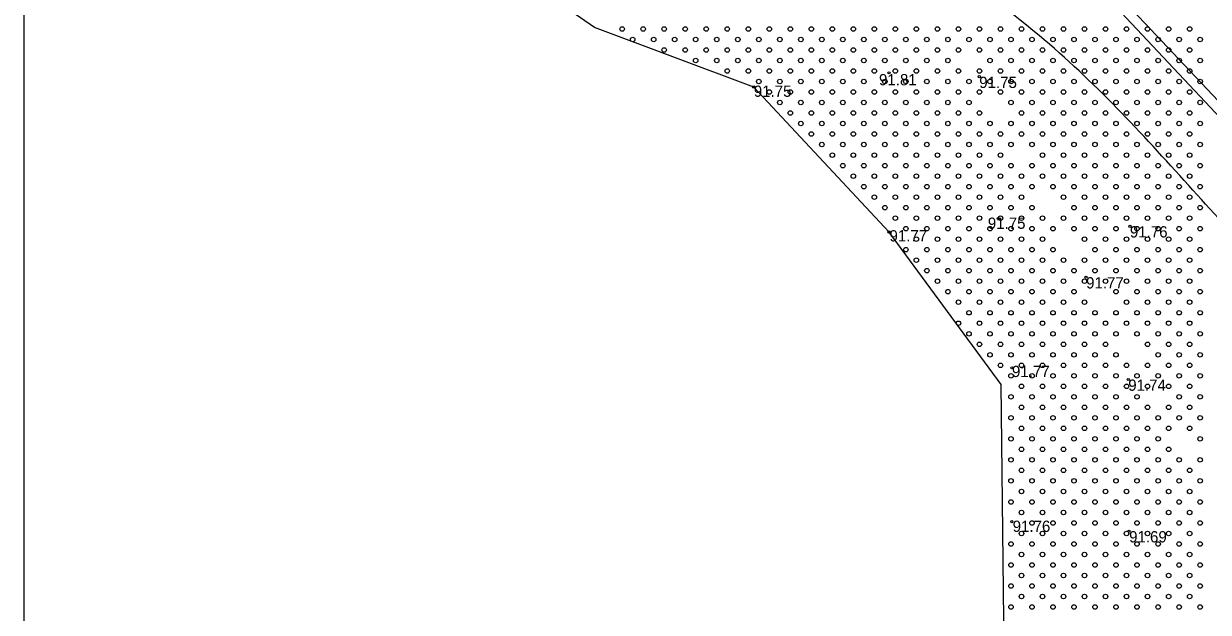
# Model space of a CAD drawing. Extents: x 316000 to 728450, y 314368 to 726000.
# Drawn here: x 725371.7 to 725766.2, y 315036.8 to 315232.8 of the extents above; entities that cross this region are included whole.
import ezdxf

# ---------------------------------------------------------------- set-up
doc = ezdxf.new("R2010")
doc.units = 0
for name, color, linetype in [('HIDG_GRAV_####_####_#', 7, 'Continuous'), ('RAMI_PLAN_####_TKST_#', 7, 'Continuous'), ('RAMI_UZMR_####_####_#', 7, 'Continuous'), ('RELJ_AATZ_####_TKST_#', 7, 'Continuous'), ('RELJ_ELEM_####_####_#', 7, 'Continuous'), ('RELJ_HORZ_PAMT_####_#', 7, 'Continuous'), ('RELJ_NOGA_####_####_#', 7, 'Continuous'), ('TERT_ELEM_####_####_#', 7, 'Continuous'), ('TERT_KONT_####_####_#', 7, 'Continuous')]:
    doc.layers.add(name, color=color, linetype=linetype)

msp = doc.modelspace()

# ---------------------------------------------------------------- linework, layer by layer
at = {"layer": 'HIDG_GRAV_####_####_#'}
for points in [[(725550.64, 315437.37), (725654.91, 315324.09), (725793.17, 315176.93), (726030.02, 314925.45), (726035.1, 314929.94), (725796.17, 315178.83)], [(725655.9, 315327.28), (725718.48, 315261.22), (725796.17, 315178.83)]]:
    msp.add_lwpolyline(points, dxfattribs=at)
at = {"layer": 'RAMI_PLAN_####_TKST_#'}
msp.add_lwpolyline([(725371.66, 314368.28), (727955.92, 314368.28), (727955.92, 316766.42), (725371.66, 316766.42)], close=True, dxfattribs=at)
at = {"layer": 'RAMI_UZMR_####_####_#'}
msp.add_lwpolyline([(727254.69, 315085.95), (727002.7, 315002.84), (726508.21, 314868.03), (726416.7, 314837.05), (725982.38, 314530.96), (725916.44, 314513.26), (725799.16, 314549.2), (725735.9, 314623.63), (725701.82, 314711.1), (725697.25, 315112.64), (725659.91, 315163.35), (725614.81, 315211.65), (725561.8, 315231.45), (725500.09, 315274.21), (725474.77, 315308.26), (725484.26, 315374.77), (725505.03, 315405.04), (725554.87, 315404.25), (725559.14, 315567.14), (725558.67, 315591.68), (725662, 315676.73), (726089.69, 315915.19)], dxfattribs=at)
at = {"layer": 'RELJ_ELEM_####_####_#'}
for centre in [(725659.91, 315216.38), (725689.93, 315215.09), (725614.81, 315211.65), (725696.3, 315167.87), (725659.91, 315163.35), (725740.11, 315165.31), (725725.51, 315148.34), (725700.78, 315118.15), (725739.55, 315114.26), (725700.78, 315066.95), (725739.84, 315063.77)]:
    msp.add_circle(centre, 0.375, dxfattribs=at)
at = {"layer": 'RELJ_HORZ_PAMT_####_#'}
msp.add_spline([(726081.57, 315247.05), (726057.5, 315241.5), (726036.5, 315213.5), (725977, 315161), (725966.5, 315108.5), (725903.5, 315045.5), (725862.12, 315076.6), (725805.5, 315130), (725759.7, 315178.88), (725709.89, 315228.8), (725646.99, 315287.19), (725634.68, 315314.96), (725629.04, 315327.48), (725557.35, 315340.26), (725478.3, 315344.16)], degree=3, dxfattribs=at)
at = {"layer": 'RELJ_NOGA_####_####_#'}
for points in [[(726259.12, 315084.51), (726262.72, 315089.26), (726261.56, 315090.84), (726260.2, 315092.42), (726257.29, 315095.53), (726218.91, 315136.38), (726180.31, 315176.84), (726128.67, 315229.97), (726063.7, 315298.11), (725999.9, 315366.09), (725937.21, 315432.09), (725876.35, 315495.23), (725810.58, 315563.08), (725744.7, 315632.91)], [(725740.86, 315626.98), (725805.54, 315558.12), (725870.39, 315491.15), (725932.8, 315426.8), (725994.98, 315360.84), (726059.66, 315292.12), (726075.75, 315275.46), (726092.08, 315259.04), (726108.47, 315242.67), (726124.69, 315226.14), (726193.27, 315154.03), (726250.06, 315092.6), (726256.32, 315085.83), (726258.82, 315084.29), (726259.12, 315084.51)]]:
    msp.add_spline(points, degree=3, dxfattribs=at)
at = {"layer": 'TERT_ELEM_####_####_#'}
for centre in [(725571, 315231), (725578, 315231), (725585, 315231), (725592, 315231), (725599, 315231), (725606, 315231), (725613, 315231), (725620, 315231), (725627, 315231), (725634, 315231), (725641, 315231), (725648, 315231), (725655, 315231), (725662, 315231), (725669, 315231), (725676, 315231), (725683, 315231), (725690, 315231), (725697, 315231), (725704, 315231), (725711, 315231), (725718, 315231), (725725, 315231), (725732, 315231), (725739, 315231), (725746, 315231), (725753, 315231), (725760, 315231), (725574.5, 315227.5), (725581.5, 315227.5), (725588.5, 315227.5), (725595.5, 315227.5), (725602.5, 315227.5), (725609.5, 315227.5), (725616.5, 315227.5), (725623.5, 315227.5), (725630.5, 315227.5), (725637.5, 315227.5), (725644.5, 315227.5), (725651.5, 315227.5), (725658.5, 315227.5), (725665.5, 315227.5), (725672.5, 315227.5), (725679.5, 315227.5), (725686.5, 315227.5), (725693.5, 315227.5), (725700.5, 315227.5), (725707.5, 315227.5), (725714.5, 315227.5), (725721.5, 315227.5), (725728.5, 315227.5), (725735.5, 315227.5), (725742.5, 315227.5), (725749.5, 315227.5), (725756.5, 315227.5), (725763.5, 315227.5), (725585, 315224), (725592, 315224), (725595.5, 315220.5), (725599, 315224), (725602.5, 315220.5), (725606, 315224), (725609.5, 315220.5), (725613, 315224), (725616.5, 315220.5), (725620, 315224), (725623.5, 315220.5), (725627, 315224), (725630.5, 315220.5), (725634, 315224), (725637.5, 315220.5), (725641, 315224), (725644.5, 315220.5), (725648, 315224), (725651.5, 315220.5), (725655, 315224), (725658.5, 315220.5), (725662, 315224), (725665.5, 315220.5), (725669, 315224), (725672.5, 315220.5), (725676, 315224), (725679.5, 315220.5), (725683, 315224), (725690, 315224), (725693.5, 315220.5), (725697, 315224), (725700.5, 315220.5), (725704, 315224), (725707.5, 315220.5), (725711, 315224), (725714.5, 315220.5), (725718, 315224), (725721.5, 315220.5), (725725, 315224), (725728.5, 315220.5), (725732, 315224), (725735.5, 315220.5), (725739, 315224), (725742.5, 315220.5), (725746, 315224), (725749.5, 315220.5), (725753, 315224), (725756.5, 315220.5), (725760, 315224), (725763.5, 315220.5), (725606, 315217), (725613, 315217), (725620, 315217), (725627, 315217), (725634, 315217), (725641, 315217), (725648, 315217), (725655, 315217), (725662, 315217), (725669, 315217), (725676, 315217), (725683, 315217), (725690, 315217), (725697, 315217), (725704, 315217), (725711, 315217), (725718, 315217), (725725, 315217), (725732, 315217), (725739, 315217), (725746, 315217), (725753, 315217), (725760, 315217), (725616.5, 315213.5), (725623.5, 315213.5), (725630.5, 315213.5), (725637.5, 315213.5), (725644.5, 315213.5), (725651.5, 315213.5), (725658.5, 315213.5), (725665.5, 315213.5), (725672.5, 315213.5), (725679.5, 315213.5), (725686.5, 315213.5), (725693.5, 315213.5), (725700.5, 315213.5), (725707.5, 315213.5), (725714.5, 315213.5), (725721.5, 315213.5), (725728.5, 315213.5), (725735.5, 315213.5), (725742.5, 315213.5), (725749.5, 315213.5), (725756.5, 315213.5), (725763.5, 315213.5), (725620, 315210), (725627, 315210), (725634, 315210), (725641, 315210), (725648, 315210), (725655, 315210), (725662, 315210), (725669, 315210), (725676, 315210), (725683, 315210), (725690, 315210), (725697, 315210), (725704, 315210), (725711, 315210), (725718, 315210), (725725, 315210), (725732, 315210), (725739, 315210), (725746, 315210), (725753, 315210), (725760, 315210), (725623.5, 315206.5), (725630.5, 315206.5), (725637.5, 315206.5), (725644.5, 315206.5), (725651.5, 315206.5), (725658.5, 315206.5), (725665.5, 315206.5), (725672.5, 315206.5), (725679.5, 315206.5), (725686.5, 315206.5), (725700.5, 315206.5), (725707.5, 315206.5), (725714.5, 315206.5), (725721.5, 315206.5), (725728.5, 315206.5), (725735.5, 315206.5), (725742.5, 315206.5), (725749.5, 315206.5), (725756.5, 315206.5), (725763.5, 315206.5), (725627, 315203), (725634, 315203), (725641, 315203), (725648, 315203), (725655, 315203), (725662, 315203), (725669, 315203), (725676, 315203), (725683, 315203), (725690, 315203), (725704, 315203), (725711, 315203), (725718, 315203), (725725, 315203), (725732, 315203), (725739, 315203), (725746, 315203), (725753, 315203), (725760, 315203), (725630.5, 315199.5), (725637.5, 315199.5), (725644.5, 315199.5), (725651.5, 315199.5), (725658.5, 315199.5), (725665.5, 315199.5), (725672.5, 315199.5), (725679.5, 315199.5), (725686.5, 315199.5), (725693.5, 315199.5), (725700.5, 315199.5), (725707.5, 315199.5), (725714.5, 315199.5), (725721.5, 315199.5), (725728.5, 315199.5), (725735.5, 315199.5), (725742.5, 315199.5), (725749.5, 315199.5), (725756.5, 315199.5), (725763.5, 315199.5), (725634, 315196), (725641, 315196), (725648, 315196), (725655, 315196), (725662, 315196), (725669, 315196), (725676, 315196), (725683, 315196), (725690, 315196), (725697, 315196), (725704, 315196), (725711, 315196), (725718, 315196), (725725, 315196), (725732, 315196), (725739, 315196), (725746, 315196), (725753, 315196), (725760, 315196), (725637.5, 315192.5), (725641, 315189), (725644.5, 315192.5), (725648, 315189), (725651.5, 315192.5), (725655, 315189), (725658.5, 315192.5), (725662, 315189), (725665.5, 315192.5), (725669, 315189), (725672.5, 315192.5), (725676, 315189), (725679.5, 315192.5), (725683, 315189), (725686.5, 315192.5), (725690, 315189), (725693.5, 315192.5), (725697, 315189), (725700.5, 315192.5), (725707.5, 315192.5), (725711, 315189), (725714.5, 315192.5), (725718, 315189), (725721.5, 315192.5), (725725, 315189), (725728.5, 315192.5), (725732, 315189), (725735.5, 315192.5), (725739, 315189), (725742.5, 315192.5), (725746, 315189), (725749.5, 315192.5), (725753, 315189), (725756.5, 315192.5), (725760, 315189), (725763.5, 315192.5), (725644.5, 315185.5), (725651.5, 315185.5), (725658.5, 315185.5), (725665.5, 315185.5), (725672.5, 315185.5), (725679.5, 315185.5), (725686.5, 315185.5), (725693.5, 315185.5), (725700.5, 315185.5), (725707.5, 315185.5), (725714.5, 315185.5), (725721.5, 315185.5), (725728.5, 315185.5), (725735.5, 315185.5), (725742.5, 315185.5), (725749.5, 315185.5), (725756.5, 315185.5), (725763.5, 315185.5), (725648, 315182), (725655, 315182), (725662, 315182), (725669, 315182), (725676, 315182), (725683, 315182), (725690, 315182), (725697, 315182), (725704, 315182), (725711, 315182), (725718, 315182), (725725, 315182), (725732, 315182), (725739, 315182), (725746, 315182), (725753, 315182), (725760, 315182), (725651.5, 315178.5), (725658.5, 315178.5), (725665.5, 315178.5), (725672.5, 315178.5), (725679.5, 315178.5), (725686.5, 315178.5), (725693.5, 315178.5), (725700.5, 315178.5), (725707.5, 315178.5), (725714.5, 315178.5), (725721.5, 315178.5), (725728.5, 315178.5), (725735.5, 315178.5), (725742.5, 315178.5), (725749.5, 315178.5), (725756.5, 315178.5), (725763.5, 315178.5), (725655, 315175), (725662, 315175), (725669, 315175), (725676, 315175), (725683, 315175), (725690, 315175), (725697, 315175), (725704, 315175), (725718, 315175), (725725, 315175), (725732, 315175), (725739, 315175), (725746, 315175), (725753, 315175), (725760, 315175), (725658.5, 315171.5), (725665.5, 315171.5), (725672.5, 315171.5), (725679.5, 315171.5), (725686.5, 315171.5), (725693.5, 315171.5), (725700.5, 315171.5), (725707.5, 315171.5), (725721.5, 315171.5), (725728.5, 315171.5), (725735.5, 315171.5), (725742.5, 315171.5), (725749.5, 315171.5), (725756.5, 315171.5), (725763.5, 315171.5), (725662, 315168), (725669, 315168), (725676, 315168), (725683, 315168), (725690, 315168), (725697, 315168), (725704, 315168), (725711, 315168), (725718, 315168), (725725, 315168), (725732, 315168), (725739, 315168), (725746, 315168), (725753, 315168), (725760, 315168), (725665.5, 315164.5), (725672.5, 315164.5), (725679.5, 315164.5), (725686.5, 315164.5), (725693.5, 315164.5), (725700.5, 315164.5), (725707.5, 315164.5), (725714.5, 315164.5), (725721.5, 315164.5), (725728.5, 315164.5), (725735.5, 315164.5), (725742.5, 315164.5), (725749.5, 315164.5), (725756.5, 315164.5), (725763.5, 315164.5), (725665.5, 315157.5), (725669, 315161), (725672.5, 315157.5), (725676, 315161), (725679.5, 315157.5), (725683, 315161), (725686.5, 315157.5), (725690, 315161), (725693.5, 315157.5), (725697, 315161), (725700.5, 315157.5), (725704, 315161), (725707.5, 315157.5), (725711, 315161), (725714.5, 315157.5), (725725, 315161), (725728.5, 315157.5), (725732, 315161), (725735.5, 315157.5), (725739, 315161), (725742.5, 315157.5), (725746, 315161), (725749.5, 315157.5), (725753, 315161), (725756.5, 315157.5), (725760, 315161), (725763.5, 315157.5), (725669, 315154), (725676, 315154), (725683, 315154), (725690, 315154), (725697, 315154), (725704, 315154), (725711, 315154), (725718, 315154), (725725, 315154), (725732, 315154), (725739, 315154), (725746, 315154), (725753, 315154), (725760, 315154), (725672.5, 315150.5), (725679.5, 315150.5), (725686.5, 315150.5), (725693.5, 315150.5), (725700.5, 315150.5), (725707.5, 315150.5), (725714.5, 315150.5), (725721.5, 315150.5), (725728.5, 315150.5), (725735.5, 315150.5), (725742.5, 315150.5), (725749.5, 315150.5), (725756.5, 315150.5), (725763.5, 315150.5), (725676, 315147), (725683, 315147), (725690, 315147), (725697, 315147), (725704, 315147), (725711, 315147), (725718, 315147), (725725, 315147), (725732, 315147), (725739, 315147), (725746, 315147), (725753, 315147), (725760, 315147), (725679.5, 315143.5), (725686.5, 315143.5), (725693.5, 315143.5), (725700.5, 315143.5), (725707.5, 315143.5), (725714.5, 315143.5), (725721.5, 315143.5), (725735.5, 315143.5), (725742.5, 315143.5), (725749.5, 315143.5), (725756.5, 315143.5), (725763.5, 315143.5), (725683, 315140), (725690, 315140), (725697, 315140), (725704, 315140), (725711, 315140), (725718, 315140), (725725, 315140), (725739, 315140), (725746, 315140), (725753, 315140), (725760, 315140), (725686.5, 315136.5), (725693.5, 315136.5), (725700.5, 315136.5), (725707.5, 315136.5), (725714.5, 315136.5), (725721.5, 315136.5), (725728.5, 315136.5), (725735.5, 315136.5), (725742.5, 315136.5), (725749.5, 315136.5), (725756.5, 315136.5), (725763.5, 315136.5), (725683, 315133), (725686.5, 315129.5), (725690, 315133), (725693.5, 315129.5), (725697, 315133), (725700.5, 315129.5), (725704, 315133), (725707.5, 315129.5), (725711, 315133), (725714.5, 315129.5), (725718, 315133), (725721.5, 315129.5), (725725, 315133), (725728.5, 315129.5), (725732, 315133), (725735.5, 315129.5), (725739, 315133), (725742.5, 315129.5), (725746, 315133), (725749.5, 315129.5), (725753, 315133), (725756.5, 315129.5), (725760, 315133), (725763.5, 315129.5), (725690, 315126), (725697, 315126), (725704, 315126), (725711, 315126), (725718, 315126), (725725, 315126), (725732, 315126), (725746, 315126), (725753, 315126), (725760, 315126), (725693.5, 315122.5), (725700.5, 315122.5), (725707.5, 315122.5), (725714.5, 315122.5), (725721.5, 315122.5), (725728.5, 315122.5), (725735.5, 315122.5), (725749.5, 315122.5), (725756.5, 315122.5), (725763.5, 315122.5), (725697, 315119), (725704, 315119), (725711, 315119), (725718, 315119), (725725, 315119), (725732, 315119), (725739, 315119), (725746, 315119), (725753, 315119), (725760, 315119), (725700.5, 315115.5), (725707.5, 315115.5), (725714.5, 315115.5), (725721.5, 315115.5), (725728.5, 315115.5), (725735.5, 315115.5), (725742.5, 315115.5), (725749.5, 315115.5), (725756.5, 315115.5), (725763.5, 315115.5), (725704, 315112), (725711, 315112), (725718, 315112), (725725, 315112), (725732, 315112), (725739, 315112), (725746, 315112), (725753, 315112), (725760, 315112), (725700.5, 315108.5), (725707.5, 315108.5), (725714.5, 315108.5), (725721.5, 315108.5), (725728.5, 315108.5), (725735.5, 315108.5), (725742.5, 315108.5), (725756.5, 315108.5), (725763.5, 315108.5), (725704, 315105), (725711, 315105), (725718, 315105), (725725, 315105), (725732, 315105), (725739, 315105), (725746, 315105), (725753, 315105), (725760, 315105), (725700.5, 315101.5), (725704, 315098), (725707.5, 315101.5), (725711, 315098), (725714.5, 315101.5), (725718, 315098), (725721.5, 315101.5), (725725, 315098), (725728.5, 315101.5), (725732, 315098), (725735.5, 315101.5), (725739, 315098), (725742.5, 315101.5), (725746, 315098), (725749.5, 315101.5), (725753, 315098), (725756.5, 315101.5), (725760, 315098), (725763.5, 315101.5), (725700.5, 315094.5), (725707.5, 315094.5), (725714.5, 315094.5), (725721.5, 315094.5), (725728.5, 315094.5), (725735.5, 315094.5), (725742.5, 315094.5), (725749.5, 315094.5), (725763.5, 315094.5), (725704, 315091), (725711, 315091), (725718, 315091), (725725, 315091), (725732, 315091), (725739, 315091), (725746, 315091), (725753, 315091), (725700.5, 315087.5), (725707.5, 315087.5), (725714.5, 315087.5), (725721.5, 315087.5), (725728.5, 315087.5), (725735.5, 315087.5), (725742.5, 315087.5), (725749.5, 315087.5), (725756.5, 315087.5), (725763.5, 315087.5), (725704, 315084), (725711, 315084), (725718, 315084), (725725, 315084), (725732, 315084), (725739, 315084), (725746, 315084), (725753, 315084), (725760, 315084), (725700.5, 315080.5), (725707.5, 315080.5), (725714.5, 315080.5), (725721.5, 315080.5), (725728.5, 315080.5), (725735.5, 315080.5), (725742.5, 315080.5), (725749.5, 315080.5), (725756.5, 315080.5), (725763.5, 315080.5), (725704, 315077), (725711, 315077), (725718, 315077), (725725, 315077), (725732, 315077), (725739, 315077), (725746, 315077), (725753, 315077), (725760, 315077), (725700.5, 315073.5), (725707.5, 315073.5), (725714.5, 315073.5), (725721.5, 315073.5), (725728.5, 315073.5), (725735.5, 315073.5), (725742.5, 315073.5), (725749.5, 315073.5), (725756.5, 315073.5), (725763.5, 315073.5), (725704, 315070), (725707.5, 315066.5), (725711, 315070), (725714.5, 315066.5), (725718, 315070), (725721.5, 315066.5), (725725, 315070), (725728.5, 315066.5), (725732, 315070), (725735.5, 315066.5), (725739, 315070), (725742.5, 315066.5), (725746, 315070), (725749.5, 315066.5), (725753, 315070), (725756.5, 315066.5), (725760, 315070), (725763.5, 315066.5), (725704, 315063), (725711, 315063), (725718, 315063), (725725, 315063), (725732, 315063), (725739, 315063), (725746, 315063), (725753, 315063), (725760, 315063), (725700.5, 315059.5), (725707.5, 315059.5), (725714.5, 315059.5), (725721.5, 315059.5), (725728.5, 315059.5), (725735.5, 315059.5), (725742.5, 315059.5), (725749.5, 315059.5), (725756.5, 315059.5), (725763.5, 315059.5), (725704, 315056), (725711, 315056), (725718, 315056), (725725, 315056), (725732, 315056), (725739, 315056), (725746, 315056), (725753, 315056), (725760, 315056), (725700.5, 315052.5), (725707.5, 315052.5), (725714.5, 315052.5), (725721.5, 315052.5), (725728.5, 315052.5), (725735.5, 315052.5), (725742.5, 315052.5), (725749.5, 315052.5), (725756.5, 315052.5), (725763.5, 315052.5), (725704, 315049), (725711, 315049), (725718, 315049), (725725, 315049), (725732, 315049), (725739, 315049), (725746, 315049), (725753, 315049), (725760, 315049), (725700.5, 315045.5), (725707.5, 315045.5), (725714.5, 315045.5), (725721.5, 315045.5), (725728.5, 315045.5), (725735.5, 315045.5), (725742.5, 315045.5), (725749.5, 315045.5), (725756.5, 315045.5), (725763.5, 315045.5), (725704, 315042), (725711, 315042), (725718, 315042), (725725, 315042), (725732, 315042), (725739, 315042), (725746, 315042), (725753, 315042), (725760, 315042), (725700.5, 315038.5), (725707.5, 315038.5), (725714.5, 315038.5), (725721.5, 315038.5), (725728.5, 315038.5), (725735.5, 315038.5), (725742.5, 315038.5), (725749.5, 315038.5), (725756.5, 315038.5), (725763.5, 315038.5)]:
    msp.add_circle(centre, 0.75, dxfattribs=at)
at = {"layer": 'TERT_KONT_####_####_#'}
msp.add_spline([(726171.05, 315177.78), (726060.22, 315058.34), (726046.85, 314926.57), (725966, 314840.49), (725918.95, 314808.85), (725841.04, 314808.85), (725695.46, 314898.17)], degree=3, dxfattribs=at)

# ---------------------------------------------------------------- texts
at = {"layer": 'RELJ_AATZ_####_TKST_#'}
for s, p in [('91.81', (725656.54, 315212.23)), ('91.75', (725689.93, 315211.34)), ('91.75', (725614.84, 315208.39)), ('91.75', (725692.79, 315164.44)), ('91.77', (725660.02, 315160.25)), ('91.76', (725740.11, 315161.56)), ('91.77', (725725.51, 315144.59)), ('91.77', (725700.83, 315115.08)), ('91.74', (725739.55, 315110.51)), ('91.76', (725701.06, 315063.52)), ('91.69', (725739.84, 315060.02))]:
    msp.add_text(s, height=3.75, dxfattribs=at).set_placement(p)

doc.saveas('drawing.dxf')
